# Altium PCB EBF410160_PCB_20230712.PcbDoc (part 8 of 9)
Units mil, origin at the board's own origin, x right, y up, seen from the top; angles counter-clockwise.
Board outline 5393.69 x 3858.26 mil, 6 copper layers (TOP, GND02, ART03, POW04, GND05, BOTTOM), stack 47.2 mil thick; 572 components, 434 nets, 2057 pads, 1177 vias.
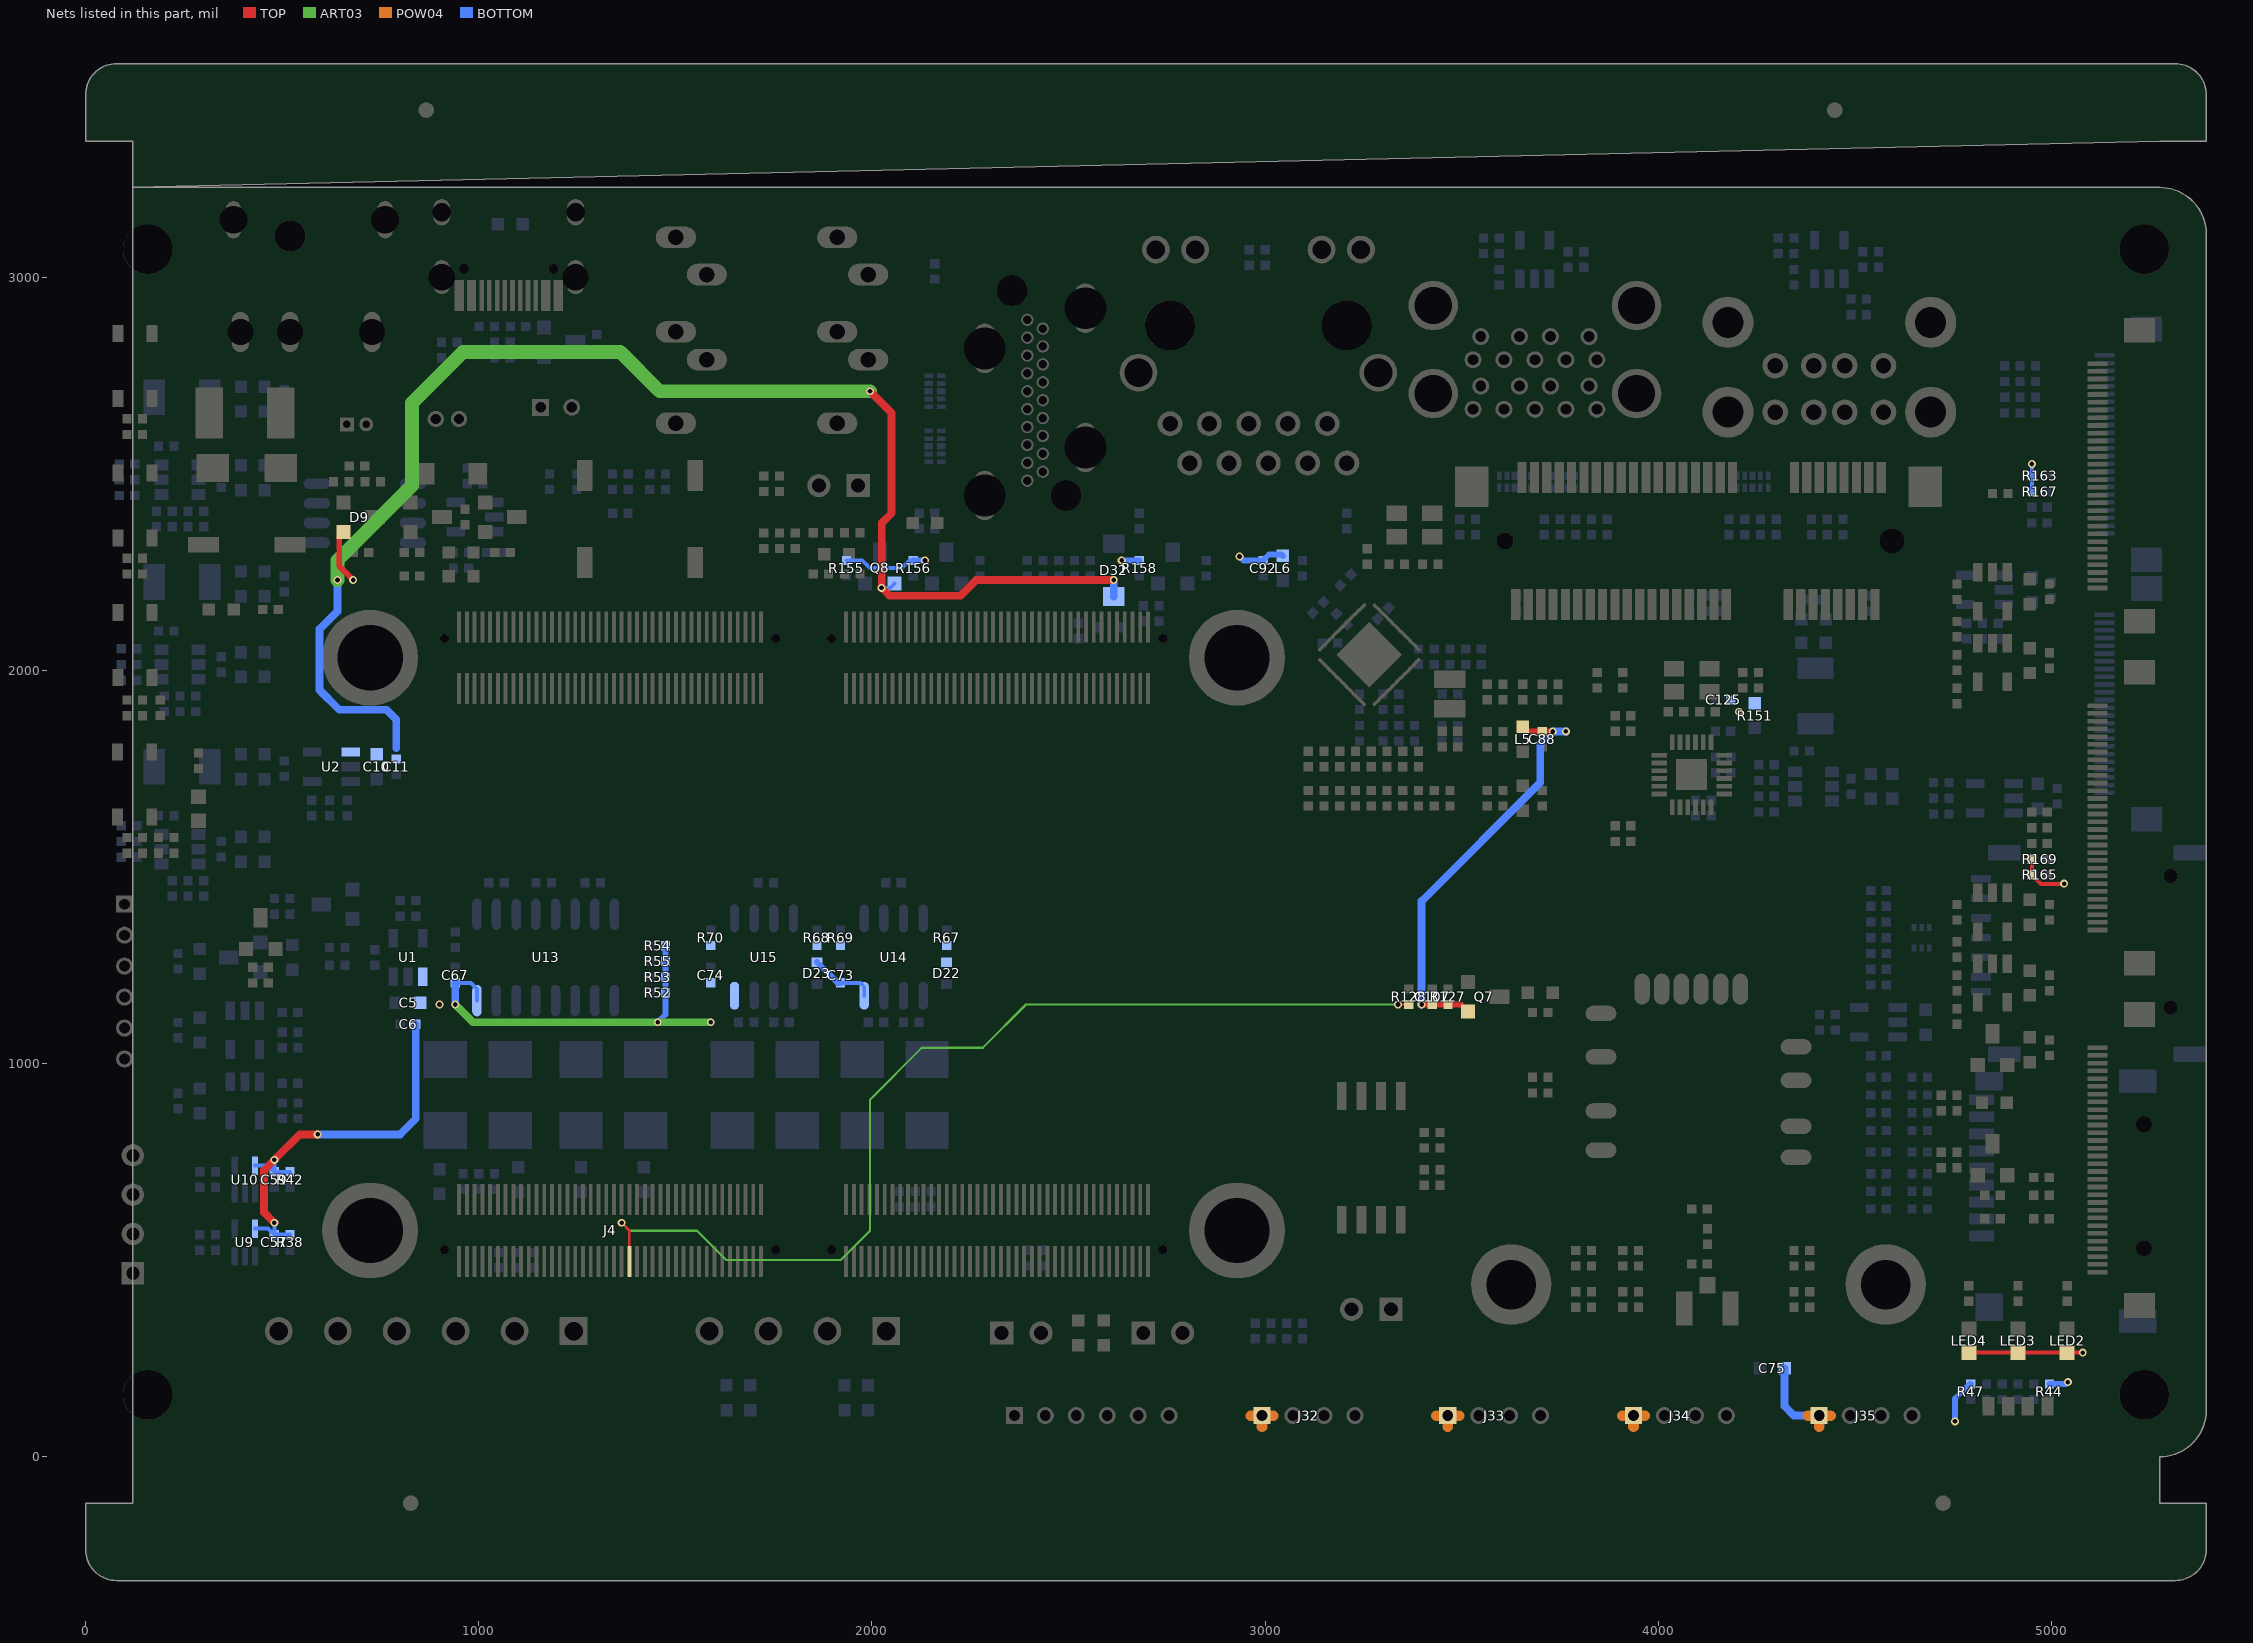
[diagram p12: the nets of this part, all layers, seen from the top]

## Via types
v1: diameter 20, hole 12, TOP to BOTTOM, 1177 vias

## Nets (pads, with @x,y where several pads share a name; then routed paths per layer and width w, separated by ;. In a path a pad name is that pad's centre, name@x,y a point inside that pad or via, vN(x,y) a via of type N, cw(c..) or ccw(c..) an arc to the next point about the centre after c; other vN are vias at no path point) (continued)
VDD_3V3: C5.1 C6.1 C57.1 C59.1 C67.1 C73.1 C74.1 C75.1 C88.1 C92.1 C107.1 C125.1 D9.2 D22.2 D23.2 J32.1 J33.1 J34.1 J35.1 L5.2 L6.2 LED2.2 LED3.2 LED4.2 Q7.2 R38.1 R42.1 R44.1 R47.2 R52.1 R53.1 R54.1 R55.1 R67.1 R68.1 R69.1 R70.1 R127.1 R151.1 R155.1 R156.1 R158.1 R163.1 R165.1 R167.1 R169.1 U1.1 U9.5 U10.5 U13.16 U14.8 U15.8 | length 5054.7
  TOP w10: LED4.2@4790,264.69 LED3.2@4915,264.69 LED2.2@5040,264.69 v1(5079.69,264.69) ; R169.1@4950.32,1520 R165.1@4950.32,1480 4973.12,1457.2 5031.85,1457.2 v1(5032.32,1457.68)
  TOP w15: D9.2@656,2352.5 645,2341.5 645,2265.32 v1(680.32,2230) ; v1(3398.2,1150.32) C107.1@3425,1150.32 R127.1@3465,1150.32 3498.18,1150.32 Q7.2@3516,1132.5 ; L5.2@3655,1856.5 3666.82,1844.68 C88.1@3705,1844.68 v1(3731.8,1844.68)
  TOP w20: v1(480,595) 454,621 454,729 v1(480,755) 545,820 v1(590,820)
  ART03 w20: v1(940,1150) 985,1105 v1(1455,1105) v1(1590,1105)
  POW04 w27: J32.1@2963.46,104.49 J32.1@2992.12,104.49 ; J32.1@2992.12,75.83 J32.1@2992.12,104.49 ; J32.1@3020.78,104.49 J32.1@2992.12,104.49 ; J33.1@3435.9,104.49 J33.1@3464.56,104.49 ; J33.1@3464.56,75.83 J33.1@3464.56,104.49 ; J33.1@3493.22,104.49 J33.1@3464.56,104.49 ; J34.1@3908.34,104.49 J34.1@3937,104.49 ; J34.1@3937,75.83 J34.1@3937,104.49 ; J34.1@3965.66,104.49 J34.1@3937,104.49 ; J35.1@4380.78,104.49 J35.1@4409.44,104.49 ; J35.1@4409.44,75.83 J35.1@4409.44,104.49 ; J35.1@4438.1,104.49 J35.1@4409.44,104.49
  BOTTOM w10: U9.5@430.59,580.43 464.25,580.43 C57.1@480,564.68 ; U10.5@430.59,740.43 464.25,740.43 C59.1@480,724.68 ; v1(480,595) C57.1@480,564.68 ; v1(480,755) C59.1@480,724.68 ; R38.1@520,564.68 C57.1@480,564.68 ; R42.1@520,724.68 C59.1@480,724.68 ; C67.1@940,1205.32 979.68,1205.32 995.2,1189.8 U13.16@995.2,1160.2 ; C73.1@1920,1205.32 1970.32,1205.32 1980.32,1195.32 U14.8@1980.32,1172.32 ; R155.1@1935,2279.68 1975.32,2279.68 1995,2260 2075.32,2260 2095,2279.68 R156.1@2105,2279.68 ; R167.1@4950.32,2455 R163.1@4950.32,2495 v1(4950.32,2525)
  BOTTOM w15: v1(1455,1105) 1474.68,1124.68 R52.1@1474.68,1180 R53.1@1474.68,1220 R55.1@1474.68,1260 R54.1@1474.68,1300 ; D23.2@1860,1257.95 1912.63,1205.32 C73.1@1920,1205.32 ; R156.1@2105,2279.68 v1(2135,2279.68) ; v1(2635,2280) 2635.32,2279.68 R158.1@2680,2279.68 ; v1(2935,2289.68) 2945,2279.68 C92.1@2995,2279.68 2995,2280 3010,2295 3041.5,2295 L6.2@3045,2291.5 ; v1(4755,90) 4755,148.01 4791.67,184.68 R47.2@4795,184.68 ; R44.1@4995,184.68 5036.8,184.68 v1(5041.8,189.68)
  BOTTOM w20: v1(590,820) 800,820 839.68,859.68 C6.1@839.68,1100 ; v1(940,1150) C67.1@940,1205.32 ; v1(3398.2,1150.32) 3398.2,1413.2 3700,1715 3700,1812.88 v1(3731.8,1844.68) 3764.68,1844.68 v1(3765,1845) ; C75.1@4321.5,225 4321.5,128.5 4345.51,104.49 J35.1@4409.44,104.49
  other v1: 900,1150 4205,1895
VDD_5V: C10.1 C11.1 D32.2 Q8.1 U2.1 | length 3614.2
  TOP w20: v1(1995,2710) 2050,2655 2050,2400 2025,2375 v1@2025,2210 ; v1(2024.5,2210) v1@2025,2210 ; v1(2615,2230) 2265,2230 2225,2190 2045,2190 v1@2025,2210
  ART03 w35: v1(640.32,2230) 640.32,2280.32 830,2470 830,2680 960,2810 1360,2810 1460,2710 v1(1995,2710)
  BOTTOM w10: v1(2024.5,2210) 2046.5,2210 Q8.1@2057.5,2221
  BOTTOM w20: v1(640.32,2230) 640.32,2150.32 595,2105 595,1950 645,1900 765,1900 790,1875 790,1802.48 ; D32.2@2615,2188.07 v1(2615,2230)
WLAN_PWR_EN: J4.45 R128.1 | length 2611.9
  TOP w6.16: v1(1363.38,595) 1383.06,575.32 J4.45@1383.06,496.81 ; v1(3338.2,1150.32) R128.1@3365,1150.32
  ART03 w5.61: v1(1363.38,595) 1383.38,575 1555,575 1630,500 1920,500 1995,575 1995,908.28 2126.72,1040 2281.72,1040 2392.03,1150.32 v1(3338.2,1150.32)
pads on no net: H1.1 H2.1 H3.1 H4.1 J1. J4. J4.33 J4.47 J4.51 J4.53 J4.55 J4.57 J4.59 J4.61 J4.63 J4.65 J4.68 J4.69 J4.70 J4.71 J4.72 J4.74 J4.75 J4.77 J4.79 J5. J6. J6.22 J6.24 J6.26 J6.28 J6.32 J6.34 J6.36 J6.38 J6.43 J6.45 J6.47 J6.49 J6.50 J6.52 J6.54 J6.56 J6.63 J6.67 J6.71 J6.73 J6.77 J7. J7.4 J7.6 J7.14 J7.16 J7.18 J7.20 J7.22 J7.24 J9.1 J12. J17. J18.14 J18.15 J18.17 J18.18 J19. J19.A8 J19.B8 J23.13 J23.14 J24.13 J24.14 J24.16 J24.17 J24.18 J24.19 J24.20 J24.21 J25.1 J25.14 J25.24 J25.25 J25.30 J27. J27.3 J27.5 J27.6 J27.16 J27.17 J27.19 J27.28 J27.30 J27.32 J27.42 J27.44 J27.45 J27.46 J27.47 J27.48 J27.49 J27.51 MARK.1 U12.1 U12.2 U17.3 U17.4 U17.9 U17.10 U17.11 U17.12 U17.13 U17.14 U22.2 U22.13 U22.17 U22.19 U22.21 U22.22 U22.23 U22.24 U25. U25.14 U36. U36.4 U36.6 U37.3

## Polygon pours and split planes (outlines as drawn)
3V3_DVDD_PHY on TOP "TOP-3V3_DVDD_PHY" (solid, pour order 36): 3520,1815 3520,1760 3525,1755 3545,1755 3550,1760 3550,1785 3555,1790 3625,1790 3640,1775 3675,1775 3675,1815 3670,1820 3525,1820 3520,1815
GND on TOP "TOP-GND" (solid, pour order 92): 33 vertices, not listed, extent 4745,1125 5020,1325
GND on TOP "TOP-GND 1" (solid, pour order 33): 5092,869 5166,869 5170,865 5170,800 5168,798 5092,798 5092,869
VDD_3V3 on TOP "TOP-VDD_3V3" (solid, pour order 26): 3635,1875 3635,1840 3645,1830 3775,1830 3780,1835 3780,1855 3775,1860 3685,1860 3670,1875 3635,1875
GND on TOP "TOP-GND 2" (solid, pour order 40): 962,2993 962,2887 955,2880 880,2880 875,2885 875,2940 880,2945 933,2945 938,2950 938,2993 962,2993
VCC_1V8 on TOP "TOP-VCC_1V8" (solid, pour order 16): 1072.89,457.62 1042.89,457.62 1042.89,538.11 1029.89,551.11 1029.89,559.89 1035,565 1079,565 1084.89,559.11 1084.89,550.89 1072.89,538.89 1072.89,457.62
5V0_IMAGE_2 on TOP "TOP-5V0_IMAGE_2" (solid, pour order 96): 4875,1278 4875,1230 4920,1230 4930,1220 4970,1220 4977,1213 5125,1213 5143,1231 5143,1385 5092,1385 5092,1283 5087,1278 4875,1278
GND on TOP "TOP-GND 3" (solid, pour order 10): 1156,2016 1156,2004 1162,1998 1162,1914 1191,1914 1191,2011 1182,2020 1160,2020 1156,2016
VCC_12V on TOP "TOP-VCC_12V" (solid, pour order 121): 32 vertices, not listed, extent 360,1330 625,2720
GND on TOP "TOP-GND 4" (solid, pour order 119): 22 vertices, not listed, extent 4000,305 4420,895
GND on TOP "TOP-GND 5" (solid, pour order 67): 2598,2151 2598,2051 2607,2042 2708,2042 2712,2046 2712,2149 2707,2154 2601,2154 2598,2151
GND on TOP "TOP-GND 6" (solid, pour order 131): 96 vertices, not listed, extent 20,20 5373.69,3208.34
GND on TOP "TOP-GND 7" (solid, pour order 20): 1004.26,536 1034.26,536 1034.26,449.74 1047.26,436.74 1047.26,428 1042.26,423 998.26,423 992.26,429 992.26,438 1004.26,450 1004.26,536
GND on TOP "TOP-GND 8" (solid, pour order 37): 2657,2001 2657,1913 2658,1912 2709,1912 2713,1916 2713,2018 2708,2023 2656,2023 2650,2017 2650,2008 2657,2001
GND on TOP "TOP-GND 9" (solid, pour order 91): 36 vertices, not listed, extent 4745,1940 5020,2140
MINIPCIE_3V3 on TOP "TOP-MINIPCIE_3V3" (solid, pour order 112): 28 vertices, not listed, extent 3626,2096 4091,2531
GND on TOP "TOP-GND 10" (solid, pour order 28): 5061,1477 5061,1436 5064,1433 5171,1433 5176,1438 5176,1457 5172,1461 5148,1461 5145,1464 5145,1482 5144,1483 5067,1483 5061,1477
3V3_EDP on TOP "TOP-3V3_EDP" (solid, pour order 25): 4983,695 5056,695 5071,680 5143,680 5143,712 5085,712 5075,722 4983,722 4983,695
GND on TOP "TOP-GND 11" (solid, pour order 53): 1003,615 1033,615 1033,700 1045,712 1045,755 1045,764 1039,770 949,770 945,766 945,755 945,711 950,706 996,706 1003,699 1003,615
3V3_IMAGE_1 on TOP "TOP-3V3_IMAGE_1" (solid, pour order 89): 4880,2295 5143,2295 5143,2263 5063,2263 5005,2205 4940,2205 4920,2225 4875,2225 4875,2290 4880,2295
GND on TOP "TOP-GND 12" (solid, pour order 38): 4930,1030 4930,960 4935,955 5005,955 5010,960 5010,1030 5005,1035 4935,1035 4930,1030
GND on TOP "TOP-GND 13" (solid, pour order 13): 980,2182 980,2161.27 974.21,2155.48 974.21,2071.48 945.21,2071.48 945.21,2168.48 945.36,2168.64 945.36,2181.36 950,2186 976,2186 980,2182
GND on TOP "TOP-GND 14" (solid, pour order 47): 22 vertices, not listed, extent 3475,1790 3620,1970
GND on TOP "TOP-GND 15" (solid, pour order 42): 1190,2993 1190,2886.86 1196.86,2880 1271.86,2880 1280,2888.14 1280,2936.86 1271.86,2945 1221.86,2945 1214,2952.86 1214,2992.86 1213.86,2993 1190,2993
VCC_1V8 on TOP "TOP-VCC_1V8 1" (solid, pour order 27): 3635,1725 3635,1690 3645,1680 3775,1680 3780,1685 3780,1705 3775,1710 3685,1710 3670,1725 3635,1725
GND on TOP "TOP-GND 16" (solid, pour order 18): 3550,1680 3615,1680 3620,1685 3620,1730 3615,1735 3555,1735 3550,1730 3550,1680
VCC5V0_SYS on TOP "TOP-VCC5V0_SYS" (solid, pour order 68): 940,694 940,458 995,458 995,694 940,694
1V8_DVDD_PHY on TOP "TOP-1V8_DVDD_PHY" (solid, pour order 57): 18 vertices, not listed, extent 3455,1625 3675,1735
3V3_IMAGE_2 on TOP "TOP-3V3_IMAGE_2" (solid, pour order 61): 4875,1458 4875,1411 4909,1411 4920,1400 4970,1400 4977,1393 5143,1393 5143,1425 5020,1425 5000,1445 4915,1445 4902,1458 4875,1458
GND on TOP "TOP-GND 17" (solid, pour order 6): 3690,1790 3775,1790 3780,1795 3780,1815 3775,1820 3690,1820 3685,1815 3685,1795 3690,1790
VCC_12V on TOP "TOP-VCC_12V 1" (solid, pour order 54): 20 vertices, not listed, extent 4708,885 4845,975
GND on TOP "TOP-GND 18" (solid, pour order 79): 24 vertices, not listed, extent 4745,1290 5015,1458
5V0_IMAGE_1 on TOP "TOP-5V0_IMAGE_1" (solid, pour order 95): 4875,2093 4875,2045 4925,2045 4940,2030 5059,2030 5070,2041 5070,2190 5083,2203 5143,2203 5143,2255 5070,2255 5030,2215 5030,2106 5017,2093 4875,2093
N17685851 on TOP "TOP-N17685851" (solid, pour order 31): 4870,976 4870,1015 4910,1015 4910,885 4870,885 4870,976
N17466585 on TOP "TOP-N17466585" (solid, pour order 45): 3370,2030 3395,2005 3425,2005 3430,2000 3430,1955 3510,1955 3510,2015 3490,2035 3375,2035 3370,2030
VCC3V3_SD on TOP "TOP-VCC3V3_SD" (solid, pour order 21): 1083,536 1113,536 1113,451 1126,438 1126,428 1121,423 1077,423 1071,429 1071,438 1083,450 1083,536
N02088 on TOP "TOP-N02088" (solid, pour order 110): 275,2930 275,2595 280,2590 350,2590 350,2770 360,2780 430,2780 440,2790 440,2930 430,2940 285,2940 275,2930
VCCA_1V8 on TOP "TOP-VCCA_1V8" (solid, pour order 11): 1043,613 1030,600 1030,590 1035,585 1045,585 1073,613 1073,694 1043,694 1043,613
1V05_PHY on TOP "TOP-1V05_PHY" (solid, pour order 50): 3430,1925 3430,1880 3425,1875 3415,1875 3410,1870 3410,1800 3420,1790 3460,1790 3465,1795 3465,1875 3470,1880 3510,1880 3510,1925 3430,1925
GND on TOP "TOP-GND 19" (solid, pour order 5): 5092,771 5092,739 5168,739 5170,741 5170,769 5168,771 5092,771
12V_EDP on TOP "TOP-12V_EDP" (solid, pour order 98): 4832,1051 5009,1051 5021,1039 5021,961 5026,956 5143,956 5143,1027 5080,1027 5076,1031 5076,1084 5059,1101 4832,1101 4832,1051
GND on TOP "TOP-GND 20" (solid, pour order 116): 380,2385 340,2345 340,2080 330,2070 236,2070 226,2080 226,2575 231,2580 370,2580 380,2570 380,2385
GND on TOP "TOP-GND 21" (solid, pour order 32): 5092,2355 5092,2303 5167,2303 5175,2295 5185,2295 5190,2300 5190,2350 5185,2355 5092,2355
GND on TOP "TOP-GND 22" (solid, pour order 78): 24 vertices, not listed, extent 4745,2105 5015,2274
GND on TOP "TOP-GND 23" (solid, pour order 43): 480,2140 580,2140 585,2145 585,2200 580,2205 485,2205 475,2195 475,2145 480,2140
FAN on TOP "TOP-FAN" (solid, pour order 55): 970,2225 1002,2225 1002,2283 1007,2288 1053,2288 1053,2367 1049,2371 980,2371 977,2374 977,2382 953,2382 953,2358 967,2358 970,2355 970,2225
GND on TOP "TOP-GND 24" (solid, pour order 7): 3690,1640 3775,1640 3780,1645 3780,1665 3775,1670 3690,1670 3685,1665 3685,1645 3690,1640
GND on TOP "TOP-GND 25" (solid, pour order 1): 18 vertices, not listed, extent 1905,2071 1940,2151
GND on TOP "TOP-GND 26" (solid, pour order 39): 4870,695 4965,695 4970,700 4970,755 4964,761 4878,761 4870,753 4870,695
"USB OTG" on TOP "TOP-USB OTG" (solid, pour order 104): 18 vertices, not listed, extent 970,2705 1182,2993
N15605755 on BOTTOM "BOTTOM-N15605755" (solid, pour order 51): 20 vertices, not listed, extent 3395,1845 3505,1965
5V0_CAM_2 on BOTTOM "BOTTOM-5V0_CAM_2" (solid, pour order 60): 4881,1701 4942,1701 4961,1682 5161,1682 5161,1734 5110,1734 5110,1715 5107,1712 4997,1712 4980,1729 4881,1729 4881,1701
GND on BOTTOM "BOTTOM-GND" (solid, pour order 35): 645,1350 645,1285 650,1280 690,1280 700,1290 700,1385 695,1390 660,1390 655,1385 655,1360 645,1350
GND on BOTTOM "BOTTOM-GND 1" (solid, pour order 62): 27 vertices, not listed, extent 3580,2970 3845,3085
VCCIO_ACODEC on BOTTOM "BOTTOM-VCCIO_ACODEC" (solid, pour order 0): 1128,508 1152,508 1152,563 1149,566 1131,566 1128,563 1128,508
VCC5V0_SYS_2 on BOTTOM "BOTTOM-VCC5V0_SYS_2" (solid, pour order 115): 26 vertices, not listed, extent 288,2415 965,2760
GND on BOTTOM "BOTTOM-GND 2" (solid, pour order 126): 21 vertices, not listed, extent 3170,305 4420,895
N18173560 on BOTTOM "BOTTOM-N18173560" (solid, pour order 82): 880,3185 880,2970 895,2955 920,2955 930,2965 930,3115 935,3120 1065,3120 1065,3150 935,3150 930,3155 930,3195 925,3200 895,3200 880,3185
VCC5V0_USB30_HOST on BOTTOM "BOTTOM-VCC5V0_USB30_HOST" (solid, pour order 77): 3760,3040 3840,3040 3845,3035 3845,2835 3835,2825 3815,2825 3800,2840 3800,2960 3790,2970 3715,2970 3710,2975 3710,3020 3740,3020 3760,3040
1V05_PHY on BOTTOM "BOTTOM-1V05_PHY" (solid, pour order 59): 23 vertices, not listed, extent 3225,1770 3430,1855
GND on BOTTOM "BOTTOM-GND 3" (solid, pour order 109): 19 vertices, not listed, extent 270,2492 605,2685
1V8_DVDD_PHY on BOTTOM "BOTTOM-1V8_DVDD_PHY" (solid, pour order 22): 3438,1742 3465,1715 3515,1715 3520,1720 3520,1730 3515,1735 3480,1735 3465,1750 3465,1835 3438,1835 3438,1742
HUB_3V3 on BOTTOM "BOTTOM-HUB_3V3" (solid, pour order 56): 4171,1866 4171,1701 4177,1695 4210,1695 4215,1700 4215,1831 4221,1837 4261,1837 4263,1839 4263,1870 4261,1872 4177,1872 4171,1866
GND on BOTTOM "BOTTOM-GND 4" (solid, pour order 8): 5084,2153 5157,2153 5161,2149 5161,2116 5086,2116 5079,2123 5079,2148 5084,2153
GND on BOTTOM "BOTTOM-GND 5" (solid, pour order 101): 4155,1935 4055,1935 4045,1925 4045,1700 4050,1695 4145,1695 4155,1705 4155,1865 4150,1870 4150,1905 4155,1910 4155,1935
VCC_12V on BOTTOM "BOTTOM-VCC_12V" (solid, pour order 100): 18 vertices, not listed, extent 270,1380 585,1540
GND on BOTTOM "BOTTOM-GND 6" (solid, pour order 86): 1024,1079 1024,943 1032,935 1128,935 1135,942 1135,1079 1129,1085 1030,1085 1024,1079
VCC_12V on BOTTOM "BOTTOM-VCC_12V 1" (solid, pour order 65): 17 vertices, not listed, extent 4424,1629 4620,1700
GND on BOTTOM "BOTTOM-GND 7" (solid, pour order 74): 1925,935 2024,935 2031,942 2031,1058 1920,1058 1920,940 1925,935
GND on BOTTOM "BOTTOM-GND 8" (solid, pour order 19): 3185,2375 3235,2375 3240,2370 3240,2315 3235,2310 3185,2310 3180,2315 3180,2370 3185,2375
GND on BOTTOM "BOTTOM-GND 9" (solid, pour order 106): 23 vertices, not listed, extent 4785,2005 5015,2217
1V05_DVDD_PHY on BOTTOM "BOTTOM-1V05_DVDD_PHY" (solid, pour order 48): 17 vertices, not listed, extent 3260,1845 3395,1915
VCC3V3_SD on BOTTOM "BOTTOM-VCC3V3_SD" (solid, pour order 3): 1083,492 1107,492 1107,458 1107,449 1111,445 1120,445 1126,439 1126,429 1121,424 1076,424 1070,430 1070,437 1083,450 1083,492
3V3_DVDD_PHY on BOTTOM "BOTTOM-3V3_DVDD_PHY" (solid, pour order 30): 3475,1835 3475,1765 3480,1760 3545,1760 3550,1765 3550,1815 3541,1824 3518,1824 3507,1835 3475,1835
GND on BOTTOM "BOTTOM-GND 10" (solid, pour order 87): 859,1079 859,943 867,935 963,935 970,942 970,1079 964,1085 865,1085 859,1079
GND on BOTTOM "BOTTOM-GND 11" (solid, pour order 73): 1760,935 1859,935 1866,942 1866,1058 1755,1058 1755,940 1760,935
GND on BOTTOM "BOTTOM-GND 12" (solid, pour order 64): 28 vertices, not listed, extent 4438,1008 4726,1137
GND on BOTTOM "BOTTOM-GND 13" (solid, pour order 108): 22 vertices, not listed, extent 3170,1925 3410,2165
GND on BOTTOM "BOTTOM-GND 14" (solid, pour order 14): 3150,2155 3130,2175 3130,2200 3165,2235 3190,2235 3210,2215 3150,2155
VCC3V3_SYS on BOTTOM "BOTTOM-VCC3V3_SYS" (solid, pour order 97): 290,2180 345,2180 345,2230 350,2235 515,2235 530,2220 585,2220 590,2225 590,2235 590,2290 585,2295 300,2295 290,2285 290,2180
GND on BOTTOM "BOTTOM-GND 15" (solid, pour order 9): 3260,1845 3260,1810 3262,1808 3353,1808 3355,1810 3355,1830 3350,1835 3285,1835 3280,1840 3280,1845 3280,1855 3275,1860 3265,1860 3260,1855 3260,1845
GND on BOTTOM "BOTTOM-GND 16" (solid, pour order 46): 20 vertices, not listed, extent 4850,1631 5067,1700
VDD_3V3 on BOTTOM "BOTTOM-VDD_3V3" (solid, pour order 102): 30 vertices, not listed, extent 1578,1095 2204,1313
VDD_3V3 on BOTTOM "BOTTOM-VDD_3V3 1" (solid, pour order 23): 4199,1885 4258,1885 4263,1890 4263,1934 4260,1937 4173,1937 4172,1936 4172,1912 4173,1911 4191,1911 4195,1907 4195,1889 4199,1885
N03641 on BOTTOM "BOTTOM-N03641" (solid, pour order 88): 20 vertices, not listed, extent 146,2001 305,2271
GND on BOTTOM "BOTTOM-GND 17" (solid, pour order 71): 2090,935 2189,935 2196,942 2196,1058 2085,1058 2085,940 2090,935
MINIPCIE_3V3 on BOTTOM "BOTTOM-MINIPCIE_3V3" (solid, pour order 107): 28 vertices, not listed, extent 4025,1980 4445,2195
VCC5V0_SYS_2 on BOTTOM "BOTTOM-VCC5V0_SYS_2 1" (solid, pour order 118): 19 vertices, not listed, extent 2170,3070 4485,3180
GND on BOTTOM "BOTTOM-GND 18" (solid, pour order 4): 1127,493 1159,493 1167,485 1167,428 1163,424 1149,424 1144,429 1144,446 1139,451 1130,451 1127,454 1127,493
3V3_AVDD_PHY on BOTTOM "BOTTOM-3V3_AVDD_PHY" (solid, pour order 76): 29 vertices, not listed, extent 3030,2035 3290,2278
VDD_3V3 on BOTTOM "BOTTOM-VDD_3V3 2" (solid, pour order 93): 23 vertices, not listed, extent 827,1088 1008,1245
GND on BOTTOM "BOTTOM-GND 19" (solid, pour order 34): 3475,1960 3475,1890 3480,1885 3540,1885 3545,1890 3545,1960 3540,1965 3480,1965 3475,1960
GND on BOTTOM "BOTTOM-GND 20" (solid, pour order 105): 25 vertices, not listed, extent 217,828 583,1005
GND on BOTTOM "BOTTOM-GND 21" (solid, pour order 75): 34 vertices, not listed, extent 723,1088 852,1387
GND on BOTTOM "BOTTOM-GND 22" (solid, pour order 29): 20 vertices, not listed, extent 1060,507 1152,609
GND on BOTTOM "BOTTOM-GND 23" (solid, pour order 94): 34 vertices, not listed, extent 4329.61,2865 4594.61,3084.76
GND on BOTTOM "BOTTOM-GND 24" (solid, pour order 15): 5110,2775 5162,2775 5163,2776 5163,2837 5156,2844 5115,2844 5109,2838 5109,2776 5110,2775
GND on BOTTOM "BOTTOM-GND 25" (solid, pour order 17): 205,1435 205,1390 210,1385 270,1385 275,1390 275,1435 270,1440 210,1440 205,1435
VCC5V0_USB20_HOST on BOTTOM "BOTTOM-VCC5V0_USB20_HOST" (solid, pour order 85): 4509.61,3039.76 4589,3039.76 4595,3033.76 4595,2872 4588,2865 4527,2865 4520,2872 4520,2959.76 4510,2969.76 4464.61,2969.76 4459.61,2974.76 4459.61,3019.76 4489.61,3019.76 4509.61,3039.76
GND on BOTTOM "BOTTOM-GND 26" (solid, pour order 72): 1595,935 1694,935 1701,942 1701,1058 1590,1058 1590,940 1595,935
GND on BOTTOM "BOTTOM-GND 27" (solid, pour order 111): 270,1569 316,1569 330,1555 515,1555 525,1565 525,1740 515,1750 365,1750 360,1745 360,1665 355,1660 275,1660 270,1655 270,1569
GND on BOTTOM "BOTTOM-GND 28" (solid, pour order 69): 29 vertices, not listed, extent 955,2280 1063,2580
VDD_5V on BOTTOM "BOTTOM-VDD_5V" (solid, pour order 58): 650,1780 715,1780 725,1770 770,1770 780,1760 805,1760 805,1830 800,1835 665,1835 650,1820 650,1780
1V05_AVDD_PHY on BOTTOM "BOTTOM-1V05_AVDD_PHY" (solid, pour order 84): 32 vertices, not listed, extent 3130,1845 3345,2225
VCC_1V8 on BOTTOM "BOTTOM-VCC_1V8" (solid, pour order 2): 1034,565 1080,565 1085,560 1085,550 1080,545 1067,545 1062,540 1062,508 1038,508 1038,542 1030,550 1030,561 1034,565
GND on BOTTOM "BOTTOM-GND 29" (solid, pour order 12): 1034,493 1065,493 1067,491 1067,431 1060,424 996,424 994,426 994,441 1001,448 1028,448 1034,454 1034,493
VCC_12V on BOTTOM "BOTTOM-VCC_12V 2" (solid, pour order 81): 540,2010 550,2000 550,1955 540,1945 335,1945 317,1963 270,1963 270,1991 316,1991 335,2010 540,2010
GND on BOTTOM "BOTTOM-GND 30" (solid, pour order 114): 21 vertices, not listed, extent 270,2020 590,2220
VCC5V0_SYS on BOTTOM "BOTTOM-VCC5V0_SYS" (solid, pour order 63): 943,695 1010,695 1015,690 1015,630 1015,550 1010,545 943,545 938,550 938,690 943,695
GND on BOTTOM "BOTTOM-GND 31" (solid, pour order 41): 950,705 1049,705 1052,708 1052,765 1047,770 950,770 945,765 945,710 950,705
GND on BOTTOM "BOTTOM-GND 32" (solid, pour order 113): 1181,1085 1472,1085 1480,1077 1480,945 1469,934 1183,934 1177,940 1177,1081 1181,1085
5V0_CAM_1 on BOTTOM "BOTTOM-5V0_CAM_1" (solid, pour order 80): 4855,2230 4925,2230 4945,2210 5080,2210 5085,2215 5085,2320 5110,2345 5160,2345 5160,2395 5100,2395 5055,2350 5055,2260 5050,2255 4855,2255 4855,2230
VCC_12V on BOTTOM "BOTTOM-VCC_12V 3" (solid, pour order 70): 331,2478 463,2478 471,2470 471,2367 464,2360 405,2360 395,2370 395,2425 386,2434 376,2434 270,2434 270,2461 314,2461 331,2478
GND on BOTTOM "BOTTOM-GND 33" (solid, pour order 103): 27 vertices, not listed, extent 217,1008 583,1185
VCC5V0_SYS on BOTTOM "BOTTOM-VCC5V0_SYS 1" (solid, pour order 99): 290,1710 345,1710 345,1750 355,1760 515,1760 525,1770 525,1890 520,1895 450,1895 440,1885 440,1835 430,1825 300,1825 290,1815 290,1710
GND on BOTTOM "BOTTOM-GND 34" (solid, pour order 136): 82 vertices, not listed, extent 20,20 5373.69,3208.34
N17423580 on BOTTOM "BOTTOM-N17423580" (solid, pour order 90): 20 vertices, not listed, extent 146,1531 305,1801
N28533 on BOTTOM "BOTTOM-N28533" (solid, pour order 83): 20 vertices, not listed, extent 147,2471 305,2740
N17592129 on BOTTOM "BOTTOM-N17592129" (solid, pour order 66): 19 vertices, not listed, extent 4355,1691 4460,1892
VCC_12V on BOTTOM "BOTTOM-VCC_12V 4" (solid, pour order 52): 500,1425 500,1295 510,1285 545,1285 555,1295 560,1300 560,1425 550,1435 545,1435 510,1435 500,1425
GND on BOTTOM "BOTTOM-GND 35" (solid, pour order 117): 25 vertices, not listed, extent 4400,1712 4620,2195
GND on BOTTOM "BOTTOM-GND 36" (solid, pour order 24): 423,537 423,479 424,478 491,478 493,480 493,537 491,539 425,539 423,537
GND on BOTTOM "BOTTOM-GND 37" (solid, pour order 49): 18 vertices, not listed, extent 369,613 495,697
GND on BOTTOM "BOTTOM-GND 38" (solid, pour order 44): 210,1250 210,1190 220,1180 310,1180 320,1190 320,1240 315,1245 260,1245 250,1255 215,1255 210,1250
3V3_EDP on POW04 "POW04-3V3_EDP" (solid, pour order 122): 20 vertices, not listed, extent 2237,255 4940,615
VCC3V3_SD on POW04 "POW04-VCC3V3_SD" (solid, pour order 124): 27 vertices, not listed, extent 1070,395 4495,970
VCC3V3_SYS on POW04 "POW04-VCC3V3_SYS" (solid, pour order 127): 55 vertices, not listed, extent 515,1190 4905,2280
VCC_12V on POW04 "POW04-VCC_12V" (solid, pour order 128): 42 vertices, not listed, extent 470,875 4784,1650
VCC_1V8 on POW04 "POW04-VCC_1V8" (solid, pour order 125): 23 vertices, not listed, extent 1030,535 3490,1265
GND on POW04 "POW04-GND" (solid, pour order 135): 82 vertices, not listed, extent 20,20 5373.69,3208.34
VCC5V0_SYS on POW04 "POW04-VCC5V0_SYS" (solid, pour order 129): 63 vertices, not listed, extent 180,120 5040,2325
VDD_3V3 on POW04 "POW04-VDD_3V3" (solid, pour order 130): 63 vertices, not listed, extent 180,50 5150,2535
GND on ART03 "ART03-GND" (solid, pour order 120): 18 vertices, not listed, extent 3995,305 4420,895
VCC5V0_SYS_2 on ART03 "ART03-VCC5V0_SYS_2" (solid, pour order 123): 22 vertices, not listed, extent 545,2700 2235,3170
GND on ART03 "ART03-GND 1" (solid, pour order 134): 82 vertices, not listed, extent 20,20 5373.69,3208.34
GND on GND02 "GND02-GND" (solid, pour order 132): 82 vertices, not listed, extent 20,20 5373.69,3208.34
GND on GND05 "GND05-GND" (solid, pour order 133): 82 vertices, not listed, extent 20,20 5373.69,3208.34

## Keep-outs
GND02:
  region: 4103.28,755.2 4103.68,764.47 4104.9,773.68 4106.9,782.73 4109.69,791.59 4113.25,800.16 4117.53,808.39 4122.52,816.22 4128.17,823.58 4134.44,830.42 4141.28,836.69 4148.64,842.34 4156.47,847.32 4164.7,851.61 4173.27,855.16 4182.12,857.95 4191.18,859.96 4200.38,861.17 4209.65,861.58 4395,861.58 4395,818.58 4209.65,818.58 4204.13,818.33 4198.65,817.61 4193.25,816.42 4187.98,814.75 4182.87,812.64 4177.97,810.08 4173.3,807.11 4168.92,803.75 4164.84,800.01 4161.11,795.94 4157.74,791.55 4154.77,786.89 4152.22,781.99 4150.1,776.88 4148.44,771.61 4147.24,766.21 4146.52,760.73 4146.28,755.2 4146.28,475 4170,475 4170,395 4146.28,395 4103.28,395 4080,395 4080,475 4103.28,475 4103.28,755.2
POW04:
  region: 4103.28,755.2 4103.68,764.47 4104.9,773.68 4106.9,782.73 4109.69,791.59 4113.25,800.16 4117.53,808.39 4122.52,816.22 4128.17,823.58 4134.44,830.42 4141.28,836.69 4148.64,842.34 4156.47,847.32 4164.7,851.61 4173.27,855.16 4182.12,857.95 4191.18,859.96 4200.38,861.17 4209.65,861.58 4395,861.58 4395,818.58 4209.65,818.58 4204.13,818.33 4198.65,817.61 4193.25,816.42 4187.98,814.75 4182.87,812.64 4177.97,810.08 4173.3,807.11 4168.92,803.75 4164.84,800.01 4161.11,795.94 4157.74,791.55 4154.77,786.89 4152.22,781.99 4150.1,776.88 4148.44,771.61 4147.24,766.21 4146.52,760.73 4146.28,755.2 4146.28,475 4170,475 4170,395 4146.28,395 4103.28,395 4080,395 4080,475 4103.28,475 4103.28,755.2
GND05:
  region: 4103.28,755.2 4103.68,764.47 4104.9,773.68 4106.9,782.73 4109.69,791.59 4113.25,800.16 4117.53,808.39 4122.52,816.22 4128.17,823.58 4134.44,830.42 4141.28,836.69 4148.64,842.34 4156.47,847.32 4164.7,851.61 4173.27,855.16 4182.12,857.95 4191.18,859.96 4200.38,861.17 4209.65,861.58 4395,861.58 4395,818.58 4209.65,818.58 4204.13,818.33 4198.65,817.61 4193.25,816.42 4187.98,814.75 4182.87,812.64 4177.97,810.08 4173.3,807.11 4168.92,803.75 4164.84,800.01 4161.11,795.94 4157.74,791.55 4154.77,786.89 4152.22,781.99 4150.1,776.88 4148.44,771.61 4147.24,766.21 4146.52,760.73 4146.28,755.2 4146.28,475 4170,475 4170,395 4146.28,395 4103.28,395 4080,395 4080,475 4103.28,475 4103.28,755.2
BOTTOM:
  region: 4103.28,755.2 4103.68,764.47 4104.9,773.68 4106.9,782.73 4109.69,791.59 4113.25,800.16 4117.53,808.39 4122.52,816.22 4128.17,823.58 4134.44,830.42 4141.28,836.69 4148.64,842.34 4156.47,847.32 4164.7,851.61 4173.27,855.16 4182.12,857.95 4191.18,859.96 4200.38,861.17 4209.65,861.58 4395,861.58 4395,818.58 4209.65,818.58 4204.13,818.33 4198.65,817.61 4193.25,816.42 4187.98,814.75 4182.87,812.64 4177.97,810.08 4173.3,807.11 4168.92,803.75 4164.84,800.01 4161.11,795.94 4157.74,791.55 4154.77,786.89 4152.22,781.99 4150.1,776.88 4148.44,771.61 4147.24,766.21 4146.52,760.73 4146.28,755.2 4146.28,475 4170,475 4170,395 4146.28,395 4103.28,395 4080,395 4080,475 4103.28,475 4103.28,755.2
Multi-Layer:
  region: 3298.68,2468.07 3298.68,3105 2665,3105 2665,2468.07 3298.68,2468.07

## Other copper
TOP:
  region net N18585723: 4092.3,132.93 4079.17,119.8 4094.48,103.72 4109.79,119.8 4096.66,132.93 4096.46,133.11 4096.25,133.28 4096.02,133.42 4095.78,133.55 4095.53,133.65 4095.28,133.73 4095.01,133.79 4094.75,133.82 4094.48,133.84 4094.21,133.82 4093.95,133.79 4093.68,133.73 4093.43,133.65 4093.18,133.55 4092.94,133.42 4092.71,133.28 4092.5,133.11 4092.3,132.93
  region net MDIN3_PHY: 2835.89,2563.75 2808.23,2558.4 2807.74,2527.05 2838.79,2528.36 2838.79,2561.35 2838.78,2561.56 2838.75,2561.77 2838.71,2561.98 2838.64,2562.18 2838.56,2562.38 2838.46,2562.57 2838.35,2562.75 2838.22,2562.92 2838.07,2563.08 2837.92,2563.22 2837.75,2563.35 2837.57,2563.46 2837.38,2563.56 2837.18,2563.64 2836.98,2563.71 2836.77,2563.75 2836.56,2563.78 2836.35,2563.79 2836.14,2563.78 2835.93,2563.75 2835.89,2563.75
  region net RS485_1_A: 2632.09,311.81 2660.47,285.47 2691.25,315 2660.47,344.53 2632.09,318.19 2631.83,317.85 2631.6,317.48 2631.4,317.09 2631.23,316.69 2631.11,316.27 2631.01,315.84 2630.96,315.41 2630.94,314.98 2630.96,314.54 2631.02,314.11 2631.12,313.68 2631.25,313.27 2631.42,312.86 2631.62,312.48 2631.86,312.11 2632.09,311.81
  pour cut-out: 4146,457 4103,457 4103,645 4146,645 4146,457
  region net MDIN1_PHY: 2906.41,2570.34 2885.86,2549.79 2908.13,2526.91 2930.4,2549.79 2909.86,2570.34 2909.7,2570.48 2909.53,2570.61 2909.35,2570.72 2909.16,2570.82 2908.96,2570.9 2908.76,2570.97 2908.55,2571.01 2908.34,2571.04 2908.13,2571.05 2907.92,2571.04 2907.71,2571.01 2907.5,2570.97 2907.3,2570.9 2907.1,2570.82 2906.91,2570.72 2906.73,2570.61 2906.56,2570.48 2906.41,2570.34
  pour cut-out: 2325,225 2290,225 2290,280 2325,280 2325,225
  pour cut-out: 2505,270 2335,270 2335,355 2505,355 2505,335 2545,335 2545,285 2505,285 2505,270
  pour cut-out: 2660,275 2595,275 2595,280 2570,280 2570,330 2600,330 2600,360 2655,360 2655,330 2660,330 2660,275
  pour cut-out: 2795,275 2705,275 2705,345 2795,345 2795,275
  pour cut-out: 1890,2255 1815,2255 1815,2290 1775,2290 1775,2335 1865,2335 1865,2370 1955,2370 1955,2260 1890,2260 1890,2255
  pour cut-out: 1764.1,2331.95 1739.38,2331.95 1739.38,2367.53 1764.1,2367.53 1764.1,2331.95
  pour cut-out: 3880,2560 3495,2560 3495,2880 3880,2880 3880,2560
  pour cut-out: 160,2600 130,2600 130,2635 160,2635 160,2600
  pour cut-out: 1160,2870 990,2870 990,2930 1160,2930 1160,2870
  pour cut-out: 1248.21,2947.22 1096.52,2947.22 1096.52,3040.77 1248.21,3040.77 1248.21,2947.22
  pour cut-out: 254 vertices and 0 holes, not listed, extent 120,55 5275,3115
  pour cut-out: 4941,74 4890,74 4890,158 4941,158 4941,74
  region net N17750554: 970.2,2628.74 970.2,2639.41 947.76,2641.17 949.53,2618.74 960.2,2618.74 961.07,2618.77 961.94,2618.89 962.79,2619.08 963.62,2619.34 964.43,2619.67 965.2,2620.08 965.94,2620.54 966.63,2621.08 967.27,2621.66 967.86,2622.31 968.39,2623 968.86,2623.74 969.26,2624.51 969.6,2625.32 969.86,2626.15 970.05,2627 970.16,2627.86 970.2,2628.74
  region net I2C4_SDA_M0: 2674.98,132.93 2661.85,119.8 2677.16,103.72 2692.47,119.8 2679.34,132.93 2679.14,133.11 2678.93,133.28 2678.7,133.42 2678.46,133.55 2678.21,133.65 2677.96,133.73 2677.69,133.79 2677.43,133.82 2677.16,133.84 2676.89,133.82 2676.63,133.79 2676.36,133.73 2676.11,133.65 2675.86,133.55 2675.62,133.42 2675.39,133.28 2675.18,133.11 2674.98,132.93
  region net N18585914: 4564.74,132.93 4551.61,119.8 4566.92,103.72 4582.23,119.8 4569.1,132.93 4568.9,133.11 4568.69,133.28 4568.46,133.42 4568.22,133.55 4567.97,133.65 4567.72,133.73 4567.45,133.79 4567.19,133.82 4566.92,133.84 4566.65,133.82 4566.39,133.79 4566.12,133.73 4565.87,133.65 4565.62,133.55 4565.38,133.42 4565.15,133.28 4564.94,133.11 4564.74,132.93
  region net MDIP1_PHY: 3056.41,2670.34 3035.86,2649.79 3058.13,2626.91 3080.4,2649.79 3059.86,2670.34 3059.7,2670.48 3059.53,2670.61 3059.35,2670.72 3059.16,2670.82 3058.96,2670.9 3058.76,2670.97 3058.55,2671.01 3058.34,2671.04 3058.13,2671.05 3057.92,2671.04 3057.71,2671.01 3057.5,2670.97 3057.3,2670.9 3057.1,2670.82 3056.91,2670.72 3056.73,2670.61 3056.56,2670.48 3056.41,2670.34
  region net N18579211: 3619.86,132.93 3606.73,119.8 3622.04,103.72 3637.35,119.8 3624.22,132.93 3624.02,133.11 3623.81,133.28 3623.58,133.42 3623.34,133.55 3623.09,133.65 3622.84,133.73 3622.57,133.79 3622.31,133.82 3622.04,133.84 3621.77,133.82 3621.51,133.79 3621.24,133.73 3620.99,133.65 3620.74,133.55 3620.5,133.42 3620.27,133.28 3620.06,133.11 3619.86,132.93
  region net B_DP1: 3643.48,2689.13 3662.23,2707.88 3647.06,2723.96 3630.92,2708.93 3638.39,2690.18 3638.5,2689.93 3638.63,2689.69 3638.78,2689.47 3638.95,2689.26 3639.14,2689.06 3639.35,2688.89 3639.57,2688.73 3639.8,2688.59 3640.05,2688.47 3640.3,2688.37 3640.56,2688.3 3640.83,2688.25 3641.1,2688.22 3641.37,2688.22 3641.64,2688.24 3641.91,2688.28 3642.18,2688.35 3642.43,2688.44 3642.68,2688.55 3642.92,2688.68 3643.14,2688.83 3643.35,2689 3643.48,2689.13
  region net N17701231: 2468.23,318.54 2450.88,335.88 2428.75,315 2450.88,294.12 2468.23,311.46 2468.52,311.79 2468.79,312.13 2469.02,312.5 2469.22,312.89 2469.39,313.29 2469.52,313.71 2469.62,314.13 2469.67,314.56 2469.69,315 2469.67,315.44 2469.62,315.87 2469.52,316.29 2469.39,316.71 2469.22,317.11 2469.02,317.5 2468.79,317.87 2468.52,318.21 2468.23,318.54
  region net N15980269: 2760.47,339.53 2760.47,315 2790.88,314.12 2790,344.53 2765.47,344.53 2765.03,344.51 2764.6,344.45 2764.18,344.36 2763.76,344.23 2763.36,344.06 2762.97,343.86 2762.6,343.63 2762.26,343.36 2761.93,343.07 2761.64,342.74 2761.37,342.4 2761.14,342.03 2760.94,341.64 2760.77,341.24 2760.64,340.82 2760.55,340.4 2760.49,339.97 2760.47,339.53
  region net VCC5V0_USB30_HOST: 3812.43,2827.52 3824.08,2827.52 3825.85,2850.94 3802.43,2849.17 3802.43,2837.52 3802.47,2836.65 3802.58,2835.78 3802.77,2834.93 3803.03,2834.1 3803.36,2833.29 3803.77,2832.52 3804.24,2831.78 3804.77,2831.09 3805.36,2830.45 3806,2829.86 3806.69,2829.33 3807.43,2828.86 3808.2,2828.45 3809.01,2828.12 3809.84,2827.86 3810.69,2827.67 3811.56,2827.56 3812.43,2827.52
  region net MIC_INP: 1861.46,2508.23 1844.12,2490.88 1865,2468.75 1885.88,2490.88 1868.54,2508.23 1868.21,2508.52 1867.87,2508.79 1867.5,2509.02 1867.11,2509.22 1866.71,2509.39 1866.29,2509.52 1865.87,2509.62 1865.44,2509.67 1865,2509.69 1864.56,2509.67 1864.13,2509.62 1863.71,2509.52 1863.29,2509.39 1862.89,2509.22 1862.5,2509.02 1862.13,2508.79 1861.79,2508.52 1861.46,2508.23
  region net N18579208: 3541.12,132.93 3527.99,119.8 3543.3,103.72 3558.61,119.8 3545.48,132.93 3545.28,133.11 3545.07,133.28 3544.84,133.42 3544.6,133.55 3544.35,133.65 3544.1,133.73 3543.83,133.79 3543.57,133.82 3543.3,133.84 3543.03,133.82 3542.77,133.79 3542.5,133.73 3542.25,133.65 3542,133.55 3541.76,133.42 3541.53,133.28 3541.32,133.11 3541.12,132.93
  region net MDIN2_PHY: 2959.86,2584.7 2980.4,2605.25 2958.13,2628.13 2935.86,2605.25 2956.41,2584.7 2956.4,2584.7 2956.56,2584.56 2956.73,2584.43 2956.91,2584.31 2957.1,2584.22 2957.3,2584.14 2957.5,2584.07 2957.71,2584.03 2957.92,2584 2958.13,2583.99 2958.34,2584 2958.55,2584.03 2958.76,2584.07 2958.96,2584.14 2959.16,2584.22 2959.35,2584.31 2959.53,2584.43 2959.7,2584.56 2959.86,2584.7
  region net N18585912: 4486,132.93 4472.87,119.8 4488.18,103.72 4503.49,119.8 4490.36,132.93 4490.16,133.11 4489.95,133.28 4489.72,133.42 4489.48,133.55 4489.23,133.65 4488.98,133.73 4488.71,133.79 4488.45,133.82 4488.18,133.84 4487.91,133.82 4487.65,133.79 4487.38,133.73 4487.13,133.65 4486.88,133.55 4486.64,133.42 4486.41,133.28 4486.2,133.11 4486,132.93
  region net MDIP0_PHY: 3159.86,2584.7 3180.4,2605.25 3158.13,2628.13 3135.86,2605.25 3156.41,2584.7 3156.4,2584.7 3156.56,2584.56 3156.73,2584.43 3156.91,2584.31 3157.1,2584.22 3157.3,2584.14 3157.5,2584.07 3157.71,2584.03 3157.92,2584 3158.13,2583.99 3158.34,2584 3158.55,2584.03 3158.76,2584.07 3158.96,2584.14 3159.16,2584.22 3159.35,2584.31 3159.53,2584.43 3159.7,2584.56 3159.86,2584.7
  region net B_DM1: 3697.24,2720.99 3710.35,2707.88 3726.44,2723.19 3710.35,2738.5 3697.24,2725.39 3697.06,2725.19 3696.89,2724.98 3696.75,2724.75 3696.62,2724.51 3696.52,2724.26 3696.44,2724 3696.38,2723.73 3696.34,2723.46 3696.33,2723.19 3696.34,2722.92 3696.38,2722.65 3696.44,2722.38 3696.52,2722.12 3696.62,2721.87 3696.75,2721.63 3696.89,2721.4 3697.06,2721.19 3697.24,2720.99
  region net VCC5V0_USB30_HOST: 3802.43,2734.84 3802.43,2723.19 3825.85,2721.42 3824.08,2744.84 3812.43,2744.84 3811.56,2744.8 3810.69,2744.69 3809.84,2744.5 3809.01,2744.24 3808.2,2743.91 3807.43,2743.5 3806.69,2743.03 3806,2742.5 3805.36,2741.91 3804.77,2741.27 3804.24,2740.58 3803.77,2739.84 3803.36,2739.07 3803.03,2738.26 3802.77,2737.43 3802.58,2736.58 3802.47,2735.71 3802.43,2734.84
  region net MDIN0_PHY: 3137.19,2559.01 3108.13,2559.01 3107.7,2527.09 3139.63,2527.52 3139.63,2556.57 3139.62,2556.79 3139.59,2557 3139.54,2557.21 3139.48,2557.41 3139.4,2557.61 3139.3,2557.8 3139.18,2557.97 3139.06,2558.14 3138.91,2558.3 3138.75,2558.44 3138.59,2558.57 3138.41,2558.69 3138.22,2558.79 3138.02,2558.87 3137.82,2558.93 3137.61,2558.98 3137.4,2559.01 3137.19,2559.01
  region net I2C4_SCL_M0: 2616.99,126.14 2598.42,126.14 2597.88,103.94 2620.07,104.49 2620.07,123.06 2620.06,123.33 2620.03,123.6 2619.97,123.86 2619.89,124.12 2619.79,124.36 2619.66,124.6 2619.52,124.83 2619.35,125.04 2619.17,125.24 2618.97,125.42 2618.76,125.58 2618.53,125.73 2618.3,125.85 2618.05,125.96 2617.79,126.04 2617.53,126.1 2617.26,126.13 2616.99,126.14
  region net MDIP2_PHY: 2987.56,2570 2987.56,2538.45 3008.37,2526.96 3008.74,2557.48 2991.57,2571.87 2991.4,2572 2991.22,2572.11 2991.03,2572.21 2990.83,2572.29 2990.63,2572.36 2990.42,2572.4 2990.21,2572.43 2990,2572.44 2989.79,2572.43 2989.57,2572.4 2989.37,2572.36 2989.16,2572.29 2988.97,2572.21 2988.78,2572.11 2988.6,2572 2988.43,2571.87 2988.27,2571.72 2988.13,2571.57 2988,2571.4 2987.89,2571.22 2987.79,2571.03 2987.71,2570.83 2987.64,2570.63 2987.6,2570.42 2987.57,2570.21 2987.56,2570
  region net RS485_2_A: 2333.2,257.1 2359.53,285.47 2330,316.25 2300.47,285.47 2326.8,257.1 2327.15,256.83 2327.52,256.6 2327.91,256.4 2328.31,256.23 2328.73,256.11 2329.16,256.01 2329.59,255.96 2330.02,255.94 2330.46,255.96 2330.89,256.02 2331.32,256.12 2331.73,256.25 2332.14,256.42 2332.52,256.62 2332.89,256.86 2333.2,257.1
  region net N17975561: 668.12,2591.55 682.09,2608.26 664.37,2627.86 646.65,2608.26 660.62,2591.55 661.2,2591.25 661.81,2591 662.43,2590.8 663.07,2590.66 663.72,2590.58 664.37,2590.55 665.03,2590.58 665.68,2590.66 666.31,2590.8 666.94,2591 667.54,2591.25 668.12,2591.55
  region net MIC_INP: 1898.69,2471.72 1885.88,2484.54 1864.39,2470 1885.88,2455.46 1898.69,2468.28 1898.7,2468.27 1898.84,2468.43 1898.97,2468.6 1899.08,2468.78 1899.18,2468.97 1899.26,2469.17 1899.33,2469.37 1899.37,2469.58 1899.4,2469.79 1899.41,2470 1899.4,2470.21 1899.37,2470.42 1899.33,2470.63 1899.26,2470.83 1899.18,2471.03 1899.08,2471.22 1898.97,2471.4 1898.84,2471.57 1898.69,2471.72
  region net EDP_TP_INT: 2462.59,85.91 2462.59,104.49 2440.4,105.03 2440.94,82.83 2459.51,82.83 2459.78,82.85 2460.05,82.88 2460.31,82.94 2460.57,83.02 2460.82,83.12 2461.05,83.25 2461.28,83.39 2461.49,83.55 2461.69,83.74 2461.87,83.93 2462.04,84.15 2462.18,84.37 2462.31,84.61 2462.41,84.86 2462.49,85.12 2462.55,85.38 2462.58,85.65 2462.59,85.91
  region net MIC_INN: 1923.05,2468.53 1935.47,2456.08 1965.61,2470 1935.47,2483.92 1923.05,2471.47 1922.93,2471.29 1922.83,2471.11 1922.74,2470.91 1922.67,2470.71 1922.61,2470.51 1922.58,2470.3 1922.56,2470.08 1922.56,2469.87 1922.58,2469.66 1922.62,2469.45 1922.68,2469.24 1922.75,2469.04 1922.85,2468.85 1922.95,2468.67 1923.05,2468.53
  region net N18585721: 4013.56,132.93 4000.43,119.8 4015.74,103.72 4031.05,119.8 4017.92,132.93 4017.72,133.11 4017.51,133.28 4017.28,133.42 4017.04,133.55 4016.79,133.65 4016.54,133.73 4016.27,133.79 4016.01,133.82 4015.74,133.84 4015.47,133.82 4015.21,133.79 4014.94,133.73 4014.69,133.65 4014.44,133.55 4014.2,133.42 4013.97,133.28 4013.76,133.11 4013.56,132.93
  region net MDIP3_PHY: 2859.86,2584.7 2880.4,2605.25 2858.13,2628.13 2835.86,2605.25 2856.41,2584.7 2856.4,2584.7 2856.56,2584.56 2856.73,2584.43 2856.91,2584.31 2857.1,2584.22 2857.3,2584.14 2857.5,2584.07 2857.71,2584.03 2857.92,2584 2858.13,2583.99 2858.34,2584 2858.55,2584.03 2858.76,2584.07 2858.96,2584.14 2859.16,2584.22 2859.35,2584.31 2859.53,2584.43 2859.7,2584.56 2859.86,2584.7
ART03:
  pour cut-out: 4785,160 2890,160 2890,195 2830,195 2830,240 2260,240 2240,260 2035,260 1995,220 1340,220 1180,380 515,380 480,415 480,800 420,860 240,860 195,905 195,1500 95,1600 95,2130 125,2160 125,2580 135,2590 155,2590 165,2580 165,2555 170,2550 440,2550 505,2615 505,2710 535,2740 535,3010 602.5,3077.5 2142.5,3077.5 2155,3090 2155,3175 2165,3185 3495,3185 3540,3140 3540,3050 3575,3015 4210,3015 4270,3075 4285,3075 4290,3070 4290,3055 4230,2995 3510,2995 3455,3050 3455,3105 3435,3125 3320,3125 3305,3110 3305,2630 3340,2595 4105,2595 4105,2700 4615,2700 4800,2885 5165,2885 5250,2800 5330,2800 5350,2780 5350,1655 5160,1465 5160,930 5225,865 5225,450 5035,260 4885,260 4785,160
